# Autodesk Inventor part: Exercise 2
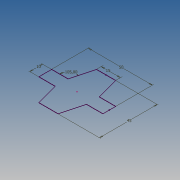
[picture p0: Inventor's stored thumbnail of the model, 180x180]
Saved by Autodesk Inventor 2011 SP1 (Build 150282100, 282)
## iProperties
Created: 2010-11
Part Number: Exercise 2
Document SubType Name: Modeling
Designer: SERGIO
Density: 1 g/cm^3
Author: SERGIO
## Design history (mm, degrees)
sketch "Sketch1"
  geometry: L1 (-25, 5)-(-25, -5); L2 (-25, -5)-(-12.189, -5); L3 (-12.189, -5)-(-7.5, -22.5); L4 (-7.5, -22.5)-(7.5, -22.5); L5 (7.5, -22.5)-(12.189, -5); L6 (12.189, -5)-(25, -5); L7 (25, -5)-(25, 5); L8 (25, 5)-(12.189, 5); L9 (12.189, 5)-(7.5, 22.5); L10 (7.5, 22.5)-(-7.5, 22.5); L11 (-7.5, 22.5)-(-12.189, 5); L12 (-12.189, 5)-(-25, 5); 3 further points
  constraints: 24 end point, 6 equal length, 6 parallel, 3 vertical alignment, 2 midpoint, 1 collinear, 1 horizontal alignment, 1 perpendicular, 1 vertical
  dimensions: "d0" = 10 distance of L1.start L1.end; "d1" = 50 distance between parallel lines of L7 L1; "d2" = 45 distance between parallel lines of L4 L10; "d3" = 15 distance of L9.end L10.end; "d4" = 105 deg angle of L12 L11
